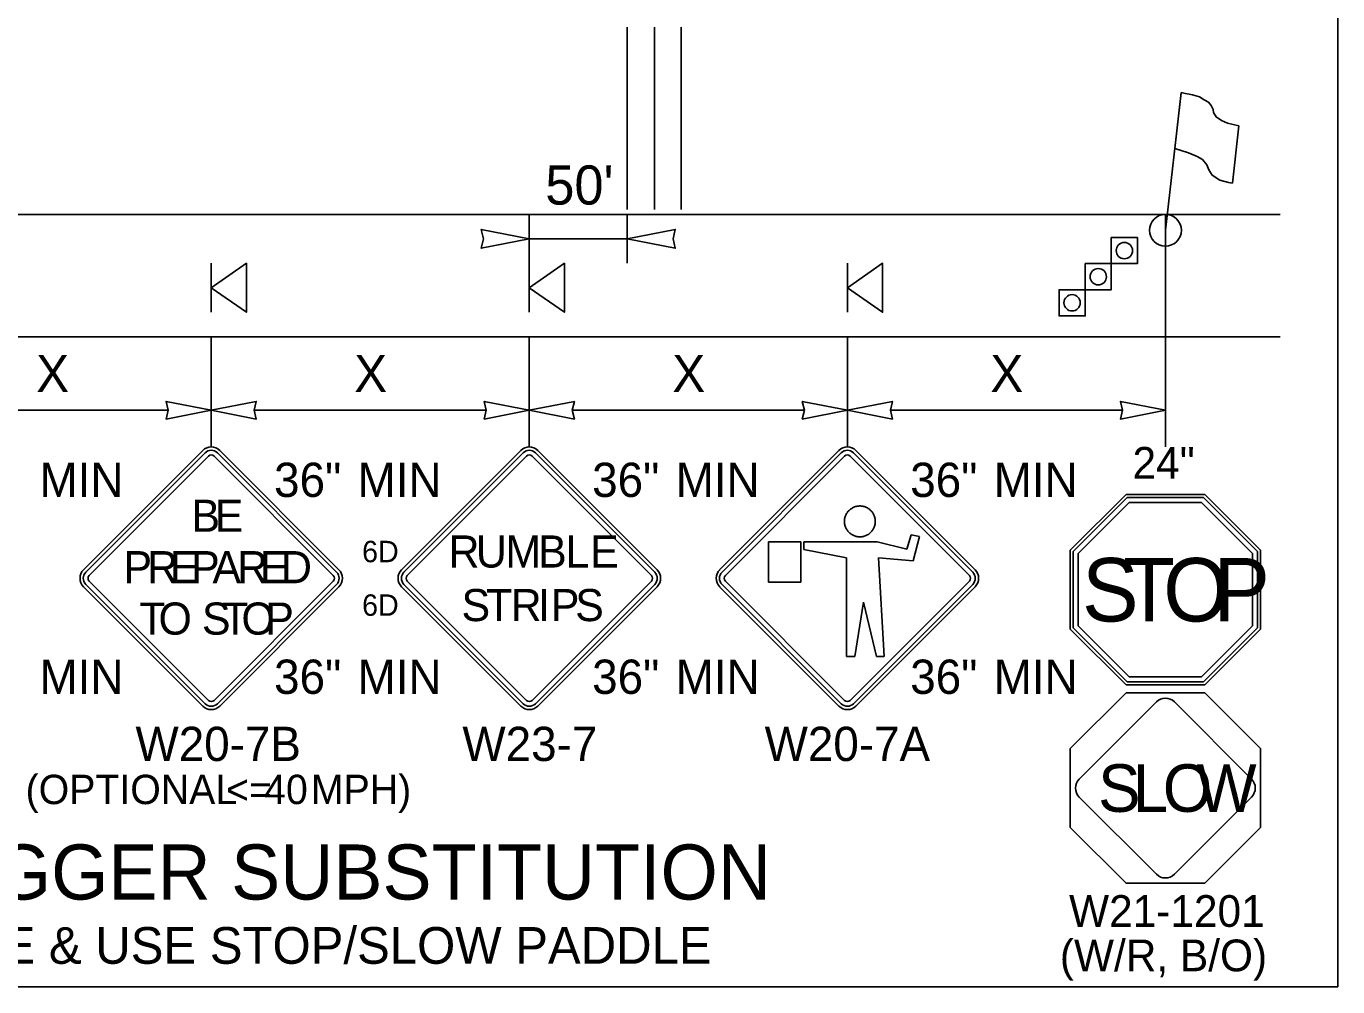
# Model space of a CAD drawing. Extents: x 99999.1 to 100095.7, y 99995 to 100010.7.
# Drawn here: x 100046.43 to 100049.11, y 100003.48 to 100005.441 of the extents above; entities that cross this region are included whole.
import ezdxf

# ---------------------------------------------------------------- set-up
doc = ezdxf.new("R2010")
doc.units = 0
for name, color, linetype in [('RD_ED_ShoulderPavedEdge', 7, 'Continuous'), ('RD_MK_LineEdgeWhite', 7, 'Continuous'), ('SH_DE_DetailHeading2Text', 7, 'Continuous'), ('TR_SN_ConstructionSigns', 7, 'Continuous'), ('TR_WZ_FlaggingStation', 7, 'Continuous'), ('TR_WZ_PortableSignMountBlk-Org', 7, 'Continuous'), ('TR_WZ_TrafficCone', 7, 'Continuous'), ('TR_WZ_WorkZoneDetails', 7, 'Continuous'), ('TR_WZ_WorkZoneTextCurrent', 7, 'Continuous')]:
    doc.layers.add(name, color=color, linetype=linetype)

msp = doc.modelspace()

# ---------------------------------------------------------------- linework, layer by layer
at = {"layer": 'RD_ED_ShoulderPavedEdge'}
msp.add_line((100045.2015, 100004.8073), (100048.9925, 100004.8073), dxfattribs=at)
at = {"layer": 'RD_MK_LineEdgeWhite'}
msp.add_line((100045.2015, 100005.0573), (100048.9925, 100005.0573), dxfattribs=at)
at = {"layer": 'TR_SN_ConstructionSigns'}
for p, q in [((100046.7907, 100004.5751), (100046.5471, 100004.3315)), ((100047.0691, 100004.3315), (100046.8255, 100004.5751)), ((100047.4407, 100004.5751), (100047.1971, 100004.3315)), ((100047.7191, 100004.3315), (100047.4755, 100004.5751)), ((100048.0907, 100004.5751), (100047.8471, 100004.3315)), ((100048.3691, 100004.3315), (100048.1255, 100004.5751)), ((100046.7955, 100004.5703), (100046.5519, 100004.3267)), ((100046.5587, 100004.3199), (100046.8023, 100004.5635)), ((100046.8139, 100004.5635), (100047.0575, 100004.3199)), ((100047.0643, 100004.3267), (100046.8207, 100004.5703)), ((100047.4455, 100004.5703), (100047.2019, 100004.3267)), ((100047.2087, 100004.3199), (100047.4523, 100004.5635)), ((100047.4639, 100004.5635), (100047.7075, 100004.3199)), ((100047.7143, 100004.3267), (100047.4707, 100004.5703)), ((100048.0955, 100004.5703), (100047.8519, 100004.3267)), ((100047.8587, 100004.3199), (100048.1023, 100004.5635)), ((100048.1139, 100004.5635), (100048.3575, 100004.3199)), ((100048.3643, 100004.3267), (100048.1207, 100004.5703)), ((100048.6775, 100004.4851), (100048.5636, 100004.3713)), ((100048.68, 100004.4791), (100048.5697, 100004.3687)), ((100048.5798, 100004.3646), (100048.6842, 100004.4689)), ((100048.8385, 100004.4851), (100048.6775, 100004.4851)), ((100048.836, 100004.4791), (100048.68, 100004.4791)), ((100048.6842, 100004.4689), (100048.8318, 100004.4689)), ((100048.8318, 100004.4689), (100048.9362, 100004.3646)), ((100048.9463, 100004.3687), (100048.836, 100004.4791)), ((100048.9524, 100004.3713), (100048.8385, 100004.4851)), ((100048.1043, 100004.4417), (100048.1037, 100004.4401)), ((100048.1049, 100004.4433), (100048.1043, 100004.4417)), ((100048.1056, 100004.4448), (100048.1049, 100004.4433)), ((100048.1064, 100004.4463), (100048.1056, 100004.4448)), ((100048.1074, 100004.4477), (100048.1064, 100004.4463)), ((100048.1083, 100004.4491), (100048.1074, 100004.4477)), ((100048.1093, 100004.4504), (100048.1083, 100004.4491)), ((100048.1104, 100004.4516), (100048.1093, 100004.4504)), ((100048.1116, 100004.4528), (100048.1104, 100004.4516)), ((100048.1128, 100004.454), (100048.1116, 100004.4528)), ((100048.1142, 100004.455), (100048.1128, 100004.454)), ((100048.1155, 100004.456), (100048.1142, 100004.455)), ((100048.1169, 100004.4569), (100048.1155, 100004.456)), ((100048.1183, 100004.4578), (100048.1169, 100004.4569)), ((100048.1199, 100004.4586), (100048.1183, 100004.4578)), ((100048.1213, 100004.4593), (100048.1199, 100004.4586)), ((100048.1229, 100004.4599), (100048.1213, 100004.4593)), ((100048.1245, 100004.4604), (100048.1229, 100004.4599)), ((100048.1262, 100004.4608), (100048.1245, 100004.4604)), ((100048.1278, 100004.4612), (100048.1262, 100004.4608)), ((100048.1294, 100004.4615), (100048.1278, 100004.4612)), ((100048.1311, 100004.4616), (100048.1294, 100004.4615)), ((100048.1328, 100004.4618), (100048.1311, 100004.4616)), ((100048.1345, 100004.4618), (100048.1328, 100004.4618)), ((100048.1361, 100004.4616), (100048.1345, 100004.4618)), ((100048.1378, 100004.4615), (100048.1361, 100004.4616)), ((100048.1395, 100004.4612), (100048.1378, 100004.4615)), ((100048.1411, 100004.4608), (100048.1395, 100004.4612)), ((100048.1427, 100004.4604), (100048.1411, 100004.4608)), ((100048.1443, 100004.4599), (100048.1427, 100004.4604)), ((100048.1459, 100004.4593), (100048.1443, 100004.4599)), ((100048.1474, 100004.4586), (100048.1459, 100004.4593)), ((100048.1489, 100004.4578), (100048.1474, 100004.4586)), ((100048.1503, 100004.4569), (100048.1489, 100004.4578)), ((100048.1517, 100004.456), (100048.1503, 100004.4569)), ((100048.1531, 100004.455), (100048.1517, 100004.456)), ((100048.1543, 100004.454), (100048.1531, 100004.455)), ((100048.1556, 100004.4528), (100048.1543, 100004.454)), ((100048.1568, 100004.4516), (100048.1556, 100004.4528)), ((100048.1579, 100004.4504), (100048.1568, 100004.4516)), ((100048.1589, 100004.4491), (100048.1579, 100004.4504)), ((100048.1599, 100004.4477), (100048.1589, 100004.4491)), ((100048.1608, 100004.4463), (100048.1599, 100004.4477)), ((100048.1616, 100004.4448), (100048.1608, 100004.4463)), ((100048.1623, 100004.4433), (100048.1616, 100004.4448)), ((100048.1629, 100004.4417), (100048.1623, 100004.4433)), ((100048.1635, 100004.4401), (100048.1629, 100004.4417)), ((100048.1023, 100004.4336), (100048.1021, 100004.4319)), ((100048.1021, 100004.4319), (100048.1021, 100004.4302)), ((100048.1021, 100004.4302), (100048.1021, 100004.4286)), ((100048.1021, 100004.4286), (100048.1023, 100004.4269)), ((100048.1025, 100004.4353), (100048.1023, 100004.4336)), ((100048.1023, 100004.4269), (100048.1025, 100004.4252)), ((100048.1028, 100004.4369), (100048.1025, 100004.4353)), ((100048.1025, 100004.4252), (100048.1028, 100004.4236)), ((100048.1032, 100004.4385), (100048.1028, 100004.4369)), ((100048.1028, 100004.4236), (100048.1032, 100004.422)), ((100048.1037, 100004.4401), (100048.1032, 100004.4385)), ((100048.1032, 100004.422), (100048.1037, 100004.4204)), ((100048.1037, 100004.4204), (100048.1043, 100004.4188)), ((100048.1043, 100004.4188), (100048.1049, 100004.4172)), ((100048.1049, 100004.4172), (100048.1056, 100004.4157)), ((100048.1056, 100004.4157), (100048.1064, 100004.4142)), ((100048.1064, 100004.4142), (100048.1074, 100004.4128)), ((100048.1599, 100004.4128), (100048.1608, 100004.4142)), ((100048.1608, 100004.4142), (100048.1616, 100004.4157)), ((100048.1616, 100004.4157), (100048.1623, 100004.4172)), ((100048.1623, 100004.4172), (100048.1629, 100004.4188)), ((100048.1629, 100004.4188), (100048.1635, 100004.4204)), ((100048.164, 100004.4385), (100048.1635, 100004.4401)), ((100048.1635, 100004.4204), (100048.164, 100004.422)), ((100048.1644, 100004.4369), (100048.164, 100004.4385)), ((100048.164, 100004.422), (100048.1644, 100004.4236)), ((100048.1647, 100004.4353), (100048.1644, 100004.4369)), ((100048.1644, 100004.4236), (100048.1647, 100004.4252)), ((100048.165, 100004.4336), (100048.1647, 100004.4353)), ((100048.1647, 100004.4252), (100048.165, 100004.4269)), ((100048.1651, 100004.4319), (100048.165, 100004.4336)), ((100048.165, 100004.4269), (100048.1651, 100004.4286)), ((100048.1651, 100004.4302), (100048.1651, 100004.4319)), ((100048.1651, 100004.4286), (100048.1651, 100004.4302)), ((100047.9469, 100004.3888), (100047.9469, 100004.306)), ((100048.0128, 100004.3888), (100047.9469, 100004.3888)), ((100048.0128, 100004.306), (100048.0128, 100004.3888)), ((100048.1689, 100004.3888), (100048.0189, 100004.3888)), ((100048.0189, 100004.3888), (100048.0189, 100004.373)), ((100048.1074, 100004.4128), (100048.1083, 100004.4114)), ((100048.1083, 100004.4114), (100048.1093, 100004.4101)), ((100048.1093, 100004.4101), (100048.1104, 100004.4089)), ((100048.1104, 100004.4089), (100048.1116, 100004.4077)), ((100048.1116, 100004.4077), (100048.1128, 100004.4065)), ((100048.1128, 100004.4065), (100048.1142, 100004.4055)), ((100048.1142, 100004.4055), (100048.1155, 100004.4044)), ((100048.1155, 100004.4044), (100048.1169, 100004.4035)), ((100048.1169, 100004.4035), (100048.1183, 100004.4027)), ((100048.1183, 100004.4027), (100048.1199, 100004.4019)), ((100048.1199, 100004.4019), (100048.1213, 100004.4012)), ((100048.1213, 100004.4012), (100048.1229, 100004.4006)), ((100048.1229, 100004.4006), (100048.1245, 100004.4001)), ((100048.1245, 100004.4001), (100048.1262, 100004.3996)), ((100048.1262, 100004.3996), (100048.1278, 100004.3993)), ((100048.1278, 100004.3993), (100048.1294, 100004.399)), ((100048.1294, 100004.399), (100048.1311, 100004.3988)), ((100048.1311, 100004.3988), (100048.1328, 100004.3987)), ((100048.1328, 100004.3987), (100048.1345, 100004.3987)), ((100048.1345, 100004.3987), (100048.1361, 100004.3988)), ((100048.1361, 100004.3988), (100048.1378, 100004.399)), ((100048.1378, 100004.399), (100048.1395, 100004.3993)), ((100048.1395, 100004.3993), (100048.1411, 100004.3996)), ((100048.1411, 100004.3996), (100048.1427, 100004.4001)), ((100048.1427, 100004.4001), (100048.1443, 100004.4006)), ((100048.1443, 100004.4006), (100048.1459, 100004.4012)), ((100048.1459, 100004.4012), (100048.1474, 100004.4019)), ((100048.1474, 100004.4019), (100048.1489, 100004.4027)), ((100048.1489, 100004.4027), (100048.1503, 100004.4035)), ((100048.1503, 100004.4035), (100048.1517, 100004.4044)), ((100048.1517, 100004.4044), (100048.1531, 100004.4055)), ((100048.1531, 100004.4055), (100048.1543, 100004.4065)), ((100048.1543, 100004.4065), (100048.1556, 100004.4077)), ((100048.1556, 100004.4077), (100048.1568, 100004.4089)), ((100048.1568, 100004.4089), (100048.1579, 100004.4101)), ((100048.1579, 100004.4101), (100048.1589, 100004.4114)), ((100048.1589, 100004.4114), (100048.1599, 100004.4128)), ((100048.2297, 100004.3738), (100048.1689, 100004.3888)), ((100048.2382, 100004.4026), (100048.2297, 100004.3738)), ((100048.2556, 100004.3995), (100048.2382, 100004.4026)), ((100048.2425, 100004.3497), (100048.2556, 100004.3995)), ((100048.0189, 100004.373), (100048.106, 100004.3557)), ((100048.5636, 100004.3713), (100048.5636, 100004.2102)), ((100048.5697, 100004.3687), (100048.5697, 100004.2127)), ((100048.5798, 100004.2169), (100048.5798, 100004.3646)), ((100048.9362, 100004.3646), (100048.9362, 100004.2169)), ((100048.9463, 100004.2127), (100048.9463, 100004.3687)), ((100048.9524, 100004.2102), (100048.9524, 100004.3713)), ((100048.106, 100004.3557), (100048.106, 100004.1541)), ((100048.1831, 100004.1541), (100048.1717, 100004.3558)), ((100048.1717, 100004.3558), (100048.2425, 100004.3497)), ((100046.8023, 100004.0647), (100046.5587, 100004.3083)), ((100047.0575, 100004.3083), (100046.8139, 100004.0647)), ((100047.4523, 100004.0647), (100047.2087, 100004.3083)), ((100047.7075, 100004.3083), (100047.4639, 100004.0647)), ((100048.1023, 100004.0647), (100047.8587, 100004.3083)), ((100048.3575, 100004.3083), (100048.1139, 100004.0647)), ((100046.5471, 100004.2967), (100046.7907, 100004.0531)), ((100046.5519, 100004.3015), (100046.7955, 100004.0579)), ((100046.8207, 100004.0579), (100047.0643, 100004.3015)), ((100046.8255, 100004.0531), (100047.0691, 100004.2967)), ((100047.1971, 100004.2967), (100047.4407, 100004.0531)), ((100047.2019, 100004.3015), (100047.4455, 100004.0579)), ((100047.4707, 100004.0579), (100047.7143, 100004.3015)), ((100047.4755, 100004.0531), (100047.7191, 100004.2967)), ((100047.8471, 100004.2967), (100048.0907, 100004.0531)), ((100047.8519, 100004.3015), (100048.0955, 100004.0579)), ((100047.9469, 100004.306), (100048.0128, 100004.306)), ((100048.1207, 100004.0579), (100048.3643, 100004.3015)), ((100048.1255, 100004.0531), (100048.3691, 100004.2967)), ((100048.1236, 100004.1541), (100048.1408, 100004.265)), ((100048.1408, 100004.265), (100048.1673, 100004.1541)), ((100048.5636, 100004.2102), (100048.6775, 100004.0963)), ((100048.5697, 100004.2127), (100048.68, 100004.1024)), ((100048.6842, 100004.1125), (100048.5798, 100004.2169)), ((100048.9362, 100004.2169), (100048.8318, 100004.1125)), ((100048.836, 100004.1024), (100048.9463, 100004.2127)), ((100048.8385, 100004.0963), (100048.9524, 100004.2102)), ((100048.106, 100004.1541), (100048.1236, 100004.1541)), ((100048.1673, 100004.1541), (100048.1831, 100004.1541)), ((100048.6775, 100004.0963), (100048.8385, 100004.0963)), ((100048.68, 100004.1024), (100048.836, 100004.1024)), ((100048.8318, 100004.1125), (100048.6842, 100004.1125)), ((100048.7397, 100004.0618), (100048.5819, 100003.9041)), ((100048.9341, 100003.9041), (100048.7763, 100004.0618)), ((100048.5819, 100003.8674), (100048.7397, 100003.7097)), ((100048.7763, 100003.7097), (100048.9341, 100003.8674))]:
    msp.add_line(p, q, dxfattribs=at)
msp.add_lwpolyline([(100048.9524, 100003.9663), (100048.9524, 100003.8052), (100048.8385, 100003.6913), (100048.6775, 100003.6913), (100048.5636, 100003.8052), (100048.5636, 100003.9663), (100048.6775, 100004.0801), (100048.8385, 100004.0801)], close=True, dxfattribs=at)
for centre, radius, start, end in [((100046.8081, 100004.5577), 0.0246, 45, 135), ((100046.8081, 100004.5577), 0.0178, 45, 135), ((100047.4581, 100004.5577), 0.0246, 45, 135), ((100047.4581, 100004.5577), 0.0178, 45, 135), ((100048.1081, 100004.5577), 0.0246, 45, 135), ((100048.1081, 100004.5577), 0.0178, 45, 135), ((100046.8081, 100004.5577), 0.0082, 45, 135), ((100047.4581, 100004.5577), 0.0082, 45, 135), ((100048.1081, 100004.5577), 0.0082, 45, 135), ((100046.5645, 100004.3141), 0.0246, 135, 225), ((100046.5645, 100004.3141), 0.0178, 135, 225), ((100046.5645, 100004.3141), 0.0082, 135, 225), ((100047.0517, 100004.3141), 0.0082, 315, 45), ((100047.0517, 100004.3141), 0.0178, 315, 45), ((100047.0517, 100004.3141), 0.0246, 315, 45), ((100047.2145, 100004.3141), 0.0246, 135, 225), ((100047.2145, 100004.3141), 0.0178, 135, 225), ((100047.2145, 100004.3141), 0.0082, 135, 225), ((100047.7017, 100004.3141), 0.0082, 315, 45), ((100047.7017, 100004.3141), 0.0178, 315, 45), ((100047.7017, 100004.3141), 0.0246, 315, 45), ((100047.8645, 100004.3141), 0.0246, 135, 225), ((100047.8645, 100004.3141), 0.0178, 135, 225), ((100047.8645, 100004.3141), 0.0082, 135, 225), ((100048.3517, 100004.3141), 0.0082, 315, 45), ((100048.3517, 100004.3141), 0.0178, 315, 45), ((100048.3517, 100004.3141), 0.0246, 315, 45), ((100048.758, 100004.0435), 0.0259, 45, 135), ((100046.8081, 100004.0705), 0.0246, 225, 315), ((100046.8081, 100004.0705), 0.0178, 225, 315), ((100046.8081, 100004.0705), 0.0082, 225, 315), ((100047.4581, 100004.0705), 0.0246, 225, 315), ((100047.4581, 100004.0705), 0.0178, 225, 315), ((100047.4581, 100004.0705), 0.0082, 225, 315), ((100048.1081, 100004.0705), 0.0246, 225, 315), ((100048.1081, 100004.0705), 0.0178, 225, 315), ((100048.1081, 100004.0705), 0.0082, 225, 315), ((100048.6003, 100003.8857), 0.0259, 135, 225), ((100048.9157, 100003.8857), 0.0259, 315, 45), ((100048.758, 100003.728), 0.0259, 225, 315)]:
    msp.add_arc(centre, radius, start, end, dxfattribs=at)
at = {"layer": 'TR_WZ_FlaggingStation'}
for p, q in [((100048.7581, 100005.0248), (100048.7901, 100005.3058)), ((100048.7771, 100005.1917), (100048.7902, 100005.3061)), ((100048.9081, 100005.2383), (100048.8948, 100005.1211)), ((100048.7771, 100005.1917), (100048.7771, 100005.1917))]:
    msp.add_line(p, q, dxfattribs=at)
for points in [[(100048.7902, 100005.3061), (100048.7959, 100005.3048), (100048.8137, 100005.3014), (100048.8276, 100005.2972), (100048.8372, 100005.2911), (100048.8458, 100005.2864), (100048.8515, 100005.2796), (100048.8557, 100005.2717), (100048.8562, 100005.2655), (100048.8616, 100005.2563), (100048.8724, 100005.2489), (100048.8848, 100005.2437), (100048.9081, 100005.2383)], [(100048.8948, 100005.1211), (100048.8867, 100005.1225), (100048.869, 100005.1271), (100048.8533, 100005.1376), (100048.8468, 100005.1482), (100048.8429, 100005.1585), (100048.8338, 100005.1694), (100048.8229, 100005.1756), (100048.8055, 100005.1827), (100048.7771, 100005.1917)]]:
    msp.add_lwpolyline(points, dxfattribs=at)
msp.add_circle((100048.7581, 100005.0248), 0.0325, dxfattribs=at)
at = {"layer": 'TR_WZ_PortableSignMountBlk-Org'}
for p, q in [((100046.8081, 100004.8574), (100046.8081, 100004.9574)), ((100047.4581, 100004.8574), (100047.4581, 100004.9574)), ((100048.1081, 100004.8574), (100048.1081, 100004.9574))]:
    msp.add_line(p, q, dxfattribs=at)
for points in [[(100046.8081, 100004.9073), (100046.8799, 100004.9574), (100046.8799, 100004.8574)], [(100047.4581, 100004.9073), (100047.5299, 100004.9574), (100047.5299, 100004.8574)], [(100048.1081, 100004.9073), (100048.1799, 100004.9574), (100048.1799, 100004.8574)]]:
    msp.add_lwpolyline(points, close=True, dxfattribs=at)
at = {"layer": 'TR_WZ_TrafficCone'}
for points in [[(100048.6474, 100005.01), (100048.7008, 100005.01), (100048.7008, 100004.9567), (100048.6474, 100004.9567), (100048.6474, 100005.01)], [(100048.6474, 100004.9567), (100048.7008, 100004.9567), (100048.7008, 100005.01), (100048.6474, 100005.01), (100048.6474, 100004.9567)], [(100048.5941, 100004.9567), (100048.6474, 100004.9567), (100048.6474, 100004.9033), (100048.5941, 100004.9033), (100048.5941, 100004.9567)], [(100048.5941, 100004.9033), (100048.6474, 100004.9033), (100048.6474, 100004.9567), (100048.5941, 100004.9567), (100048.5941, 100004.9033)], [(100048.5408, 100004.9033), (100048.5941, 100004.9033), (100048.5941, 100004.85), (100048.5408, 100004.85), (100048.5408, 100004.9033)], [(100048.5408, 100004.85), (100048.5941, 100004.85), (100048.5941, 100004.9033), (100048.5408, 100004.9033), (100048.5408, 100004.85)]]:
    msp.add_lwpolyline(points, dxfattribs=at)
for centre in [(100048.6741, 100004.9833), (100048.6208, 100004.93), (100048.5674, 100004.8767)]:
    msp.add_circle(centre, 0.0167, dxfattribs=at)
at = {"layer": 'TR_WZ_WorkZoneDetails'}
for p, q in [((100047.6581, 100005.0673), (100047.6581, 100005.4398)), ((100047.7137, 100005.0673), (100047.7137, 100005.4398)), ((100047.7686, 100005.0673), (100047.7686, 100005.4398)), ((100047.4581, 100004.9574), (100047.4581, 100005.0573)), ((100047.6581, 100005.0573), (100047.6581, 100004.9574)), ((100048.7581, 100005.0573), (100048.7581, 100004.5823)), ((100047.6581, 100005.0074), (100047.4581, 100005.0074)), ((100046.8081, 100004.8073), (100046.8081, 100004.5823)), ((100047.4581, 100004.8073), (100047.4581, 100004.5823)), ((100048.1081, 100004.8073), (100048.1081, 100004.5823)), ((100046.7202, 100004.6573), (100046.246, 100004.6573)), ((100047.3702, 100004.6573), (100046.896, 100004.6573)), ((100048.0202, 100004.6573), (100047.546, 100004.6573)), ((100048.6702, 100004.6573), (100048.196, 100004.6573))]:
    msp.add_line(p, q, dxfattribs=at)
for points in [[(100047.4581, 100005.0074), (100047.3598, 100004.9881), (100047.3644, 100005.0074), (100047.3598, 100005.0267)], [(100047.6581, 100005.0074), (100047.7564, 100004.9881), (100047.7518, 100005.0074), (100047.7564, 100005.0267)], [(100046.8081, 100004.6573), (100046.7159, 100004.6754), (100046.7202, 100004.6573), (100046.7159, 100004.6393)], [(100046.8081, 100004.6573), (100046.9002, 100004.6754), (100046.896, 100004.6573), (100046.9002, 100004.6393)], [(100047.4581, 100004.6573), (100047.3659, 100004.6754), (100047.3702, 100004.6573), (100047.3659, 100004.6393)], [(100047.4581, 100004.6573), (100047.5502, 100004.6754), (100047.546, 100004.6573), (100047.5502, 100004.6393)], [(100048.1081, 100004.6573), (100048.0159, 100004.6754), (100048.0202, 100004.6573), (100048.0159, 100004.6393)], [(100048.1081, 100004.6573), (100048.2002, 100004.6754), (100048.196, 100004.6573), (100048.2002, 100004.6393)], [(100048.7581, 100004.6573), (100048.6659, 100004.6754), (100048.6702, 100004.6573), (100048.6659, 100004.6393)]]:
    msp.add_lwpolyline(points, close=True, dxfattribs=at)
at = {"layer": 'TR_WZ_WorkZoneTextCurrent'}
msp.add_lwpolyline([(100045.1015, 100005.5823), (100049.1102, 100005.5823), (100049.1102, 100003.4799), (100045.1015, 100003.4799)], close=True, dxfattribs=at)

# ---------------------------------------------------------------- texts
at = {"layer": 'SH_DE_DetailHeading2Text'}
msp.add_text('HUMAN FLAGGER SUBSTITUTION', height=0.1125, rotation=360, dxfattribs=at).set_placement((100045.4946, 100003.658))
at = {"layer": 'TR_SN_ConstructionSigns'}
for s, height, p in [('24"', 0.0648, (100048.6908, 100004.5175)), ('B', 0.0656, (100046.7676, 100004.4091)), ('E', 0.0656, (100046.8151, 100004.4091)), ('6D', 0.04375, (100047.1164, 100004.3469)), ('R', 0.0656, (100047.293, 100004.336)), ('U', 0.0656, (100047.3488, 100004.336)), ('M', 0.0656, (100047.4092, 100004.336)), ('B', 0.0656, (100047.4761, 100004.336)), ('L', 0.0656, (100047.5319, 100004.336)), ('E', 0.0656, (100047.5824, 100004.336)), ('P', 0.0656, (100046.6288, 100004.304)), ('R', 0.0656, (100046.6771, 100004.304)), ('E', 0.0656, (100046.7237, 100004.304)), ('P', 0.0656, (100046.767, 100004.304)), ('A', 0.0656, (100046.8107, 100004.304)), ('R', 0.0656, (100046.8608, 100004.304)), ('E', 0.0656, (100046.9073, 100004.304)), ('D', 0.0656, (100046.9506, 100004.304)), ('S', 0.1296, (100048.5876, 100004.2259)), ('T', 0.1296, (100048.6718, 100004.2259)), ('O', 0.1296, (100048.7535, 100004.2259)), ('P', 0.1296, (100048.8559, 100004.2259)), ('6D', 0.04375, (100047.1164, 100004.2375)), ('S', 0.0656, (100047.3196, 100004.2266)), ('T', 0.0656, (100047.3695, 100004.2266)), ('R', 0.0656, (100047.42, 100004.2266)), ('I', 0.0656, (100047.4758, 100004.2266)), ('P', 0.0656, (100047.5021, 100004.2266)), ('S', 0.0656, (100047.5519, 100004.2266)), ('T', 0.0656, (100046.6609, 100004.199)), ('O', 0.0656, (100046.7003, 100004.199)), ('S', 0.0656, (100046.7891, 100004.199)), ('T', 0.0656, (100046.8303, 100004.199)), ('O', 0.0656, (100046.8698, 100004.199)), ('P', 0.0656, (100046.9185, 100004.199)), ('S', 0.0972, (100048.6205, 100003.8371)), ('L', 0.0972, (100048.6914, 100003.8371)), ('O', 0.0972, (100048.7527, 100003.8371)), ('W', 0.0972, (100048.8217, 100003.8371))]:
    msp.add_text(s, height=height, dxfattribs=at).set_placement(p)
for s, height, p in [('MIN', 0.07, (100046.4571, 100004.4802)), ('36"', 0.07, (100046.9365, 100004.4802)), ('MIN', 0.07, (100047.1071, 100004.4802)), ('36"', 0.07, (100047.5865, 100004.4802)), ('MIN', 0.07, (100047.7571, 100004.4802)), ('36"', 0.07, (100048.2365, 100004.4802)), ('MIN', 0.07, (100048.4071, 100004.4802)), ('MIN', 0.07, (100046.4571, 100004.078)), ('36"', 0.07, (100046.9365, 100004.078)), ('MIN', 0.07, (100047.1071, 100004.078)), ('36"', 0.07, (100047.5865, 100004.078)), ('MIN', 0.07, (100047.7571, 100004.078)), ('36"', 0.07, (100048.2365, 100004.078)), ('MIN', 0.07, (100048.4071, 100004.078)), ('W20-7B', 0.07, (100046.6533, 100003.9409)), ('W23-7', 0.07, (100047.3214, 100003.9409)), ('W20-7A', 0.07, (100047.939, 100003.9409)), ('(OPTIONAL', 0.06, (100046.4287, 100003.8529)), ('40', 0.06, (100046.9162, 100003.8529)), ('MPH)', 0.06, (100047.0117, 100003.8529)), ('<=', 0.06, (100046.8384, 100003.8529)), ('W21-1201', 0.0648, (100048.5611, 100003.6022)), ('(W/R, B/O)', 0.0648, (100048.5423, 100003.5115))]:
    msp.add_text(s, height=height, rotation=360, dxfattribs=at).set_placement(p)
at = {"layer": 'TR_WZ_WorkZoneTextCurrent'}
for s, height, p in [("50'", 0.08, (100047.4908, 100005.0773)), ('UPDATE SIGNAGE & USE STOP/SLOW PADDLE', 0.075, (100045.5568, 100003.5268))]:
    msp.add_text(s, height=height, dxfattribs=at).set_placement(p)
for p in [(100046.4505, 100004.6948), (100047.1005, 100004.6948), (100047.7505, 100004.6948), (100048.4005, 100004.6948)]:
    msp.add_text('X', height=0.075, rotation=360, dxfattribs=at).set_placement(p)

doc.saveas('drawing.dxf')
